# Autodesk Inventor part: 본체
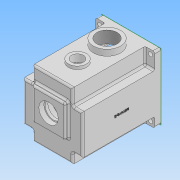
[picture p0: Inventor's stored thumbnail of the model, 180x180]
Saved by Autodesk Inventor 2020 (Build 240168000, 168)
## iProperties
Created: 2022-01
Part Number: 본체
Material: 일반
Document SubType Name: Modeling
Designer: user
Density: 1 g/cm^3
Appearance: 기본값
Author: user
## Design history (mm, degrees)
sketch "스케치1"
  geometry: L1 (-49, -55)-(49, -55); L2 (49, -55)-(49, 55); L3 (49, 55)-(-49, 55); L4 (-49, 55)-(-49, -55); L5 (-49, -55)-(49, 55); L6 (49, -55)-(-49, 55); 1 further point
  constraints: 12 end point, 2 midpoint, 2 parallel, 1 horizontal, 1 perpendicular
  dimensions: "d0" = 98 distance of L3.end L2.end; "d1" = 110 distance of L2.end L1.end
extrude "돌출1" new body sketch "스케치1" distance "d2" = 130; taper "d3" = 0 deg
sketch "스케치2"
  geometry: L1 (-49, -55)-(49, -55) reference; L2 (-27, -21)-(27, -21); L3 (27, -21)-(27, 33); L4 (27, 33)-(-27, 33); L5 (-27, 33)-(-27, -21); L6 (-27, -21)-(27, 33); L7 (27, -21)-(-27, 33); 3 further points
  constraints: 12 end point, 3 midpoint, 2 parallel, 1 horizontal, 1 perpendicular, 1 vertical alignment
  dimensions: "d4" = 54 distance of L3.end L4.end; "d5" = 54 distance of L2.end L3.end; "d7" = 61 distance from line of point (0, 6) L1
extrude "돌출2" join sketch "스케치2" distance "d8" = 7; taper "d9" = 0 deg
sketch "스케치3"
  geometry: L1 (27, 33)-(27, -21) reference; L2 (27, -21)-(-27, -21) reference; L3 (-27, -21)-(-27, 33) reference; L4 (-27, 33)-(27, 33) reference; L5 (-49, -55)-(49, -55) reference; L6 (49, -55)-(49, 55) reference; L7 (49, 55)-(-49, 55) reference; L8 (-49, 55)-(-49, -55) reference; L9 (-49, 55)-(-33, 55); L10 (-33, 55)-(-33, 28); L11 (-33, 28)-(-49, 28); L12 (-49, 28)-(-49, 55); L13 (49, 55)-(33, 55); L14 (33, 55)-(33, 28); L15 (33, 28)-(49, 28); L16 (49, 28)-(49, 55); L17 (-49, -55)-(-33, -55); L18 (-33, -55)-(-33, -38); L19 (-33, -38)-(-49, -38); L20 (-49, -38)-(-49, -55); L21 (49, -55)-(33, -55); L22 (33, -55)-(33, -38); L23 (33, -38)-(49, -38); L24 (49, -38)-(49, -55); 9 further points
  constraints: 32 end point, 8 parallel, 4 horizontal, 4 perpendicular, 1 horizontal alignment, 1 point on line
  dimensions: "d10" = 16 distance of L7.end L9.end; "d11" = 16 distance of L6.end L13.end; "d12" = 16 distance between parallel lines of L8 L18; "d13" = 16 distance between parallel lines of L6 L22; "d14" = 27 distance between parallel lines of L11 L7; "d15" = 17 distance between parallel lines of L19 L5
extrude "돌출3" cut sketch "스케치3" distance "d16" = 120; taper "d17" = 0 deg
sketch "스케치4"
  geometry: L1 (-49, -55)-(49, -55) reference; L2 (-23, 45)-(23, 45); L3 (23, 45)-(23, 30.143); L4 (-23, 30.143)-(-23, 45); A1 r 42 centre (0, -5) between (-23, 30.143) and (23, 30.143); 4 further points
  constraints: 6 end point, 2 point on circle, 2 vertical alignment, 1 centre point, 1 horizontal, 1 midpoint, 1 parallel, 1 perpendicular
  dimensions: "d18" = 50 distance from line of A1.centre L1; "d19" = 84 diameter of A1; "d20" = 50 distance from line of A1.centre L2; "d21" = 46 distance of L2.start L2.end
extrude "돌출4" cut sketch "스케치4" distance "d22" = 121; taper "d23" = 0 deg
sketch "스케치5"
  geometry: L1 (23, 45)-(23, 30.143) reference; L2 (-23, 30.143)-(-23, 45) reference; L3 (-23, 45)-(23, 45) reference; L4 (26, 31.729)-(26, 48); L5 (26, 48)-(-26, 48); L6 (-26, 48)-(-26, 31.729); A1 r 42 centre (0, -5) between (-23, 30.143) and (23, 30.143) reference; A2 r 45 centre (0, -5) between (-26, 31.729) and (26, 31.729); 1 further point
  constraints: 6 end point, 2 point on circle, 1 centre point, 3 other
  dimensions: "d24" = 3 radial gap between concentric circles of A1 A2
extrude "돌출5" cut sketch "스케치5" distance "d25" = 9; taper "d26" = 0 deg
sketch "스케치6"
  geometry: C1 r 21 at (0, 6); C2 r 15 at (0, -25); A1 r 42 centre (0, -5) between (-23, 30.143) and (23, 30.143) reference; 3 further points
  constraints: 2 centre point, 2 vertical alignment
  dimensions: "d27" = 20 distance of C2.centre A1.centre; "d28" = 11 distance of A1.centre C1.centre; "d29" = 42 diameter of C1; "d30" = 30 diameter of C2
extrude "돌출6" join sketch "스케치6" distance "d31" = 7; taper "d32" = 0 deg
sketch "스케치7"
  geometry: A1 r 15 centre (0, -25) between (-8.978, -12.984) and (8.978, -12.984) reference; 1 further point
hole "구멍1" sketch "스케치7" at (0, -25) diameter "d33" = 19; stored, may be unused: countersink angle "d37" = 90 deg, drill point angle "d39" = 0 deg; dims "d34" = 70, "d35" = 22, "d36" = 7, "d38" = 10
sketch "스케치8"
  geometry: A1 r 21 centre (0, 6) between (8.978, -12.984) and (-8.978, -12.984) reference; 2 further points
  constraints: 1 coincident
hole "구멍2" sketch "스케치8" at (0, 6) diameter "d40" = 28; stored, may be unused: countersink angle "d44" = 90 deg, drill point angle "d46" = 0 deg; dims "d41" = 70, "d42" = 35, "d43" = 10, "d45" = 10
sketch "스케치9"
  geometry: C1 r 14 at (0, 6) reference; C2 r 16 at (0, 6); 1 further point
  constraints: 1 centre point, 1 coincident
  dimensions: "d47" = 32 diameter of C2
extrude "돌출7" cut sketch "스케치9" distance "d48" = 8.3; taper "d49" = 0 deg
sketch "스케치10"
  geometry: L1 (-36, -1)-(-41.809, -1); L2 (-36, -9)-(-41.809, -9); A1 r 45 centre (0, -5) between (-26, 31.729) and (26, 31.729) reference; A2 r 42 centre (0, -5) between (-23, 30.143) and (23, 30.143) reference; A3 r 4 centre (-36, -5) between (-36, -1) and (-36, -9); A4 r 42 centre (0, -5) between (-23, 30.143) and (23, 30.143) reference; 3 further points
  constraints: 4 end point, 4 point on circle, 2 horizontal, 2 tangent, 1 centre point, 1 horizontal alignment
  dimensions: "d50" = 8 diameter of A3; "d51" = 36 distance of A3.centre A1.centre
extrude "돌출8" join sketch "스케치10" stored distance "d52" = 8.3; taper "d53" = 0 deg
sketch "스케치11"
  geometry: L1 (98, 0)-(0, 0) reference; L2 (49, 0)-(49, -40); L3 (49, -40)-(49, -89); C1 r 22.5 at (49, -40); C2 r 15 at (49, -89); 1 further point
  constraints: 4 end point, 2 centre point, 2 coincident, 1 midpoint, 1 point on line, 1 vertical
  dimensions: "d66" = 40 distance of L2.start L2.end; "d67" = 49 distance of L2.end L3.end; "d68" = 45 diameter of C1; "d69" = 30 diameter of C2
sketch "스케치12"
  geometry: L1 (-26, 48)-(26, 48) reference; L2 (-49, 55)-(-49, -55) reference; L3 (-49, 55)-(-49, 48); L4 (-49, 48)-(-42, 48); L5 (-42, 48)-(42, 48); L6 (42, 48)-(42, -48); L7 (42, -48)-(-42, -48); L8 (-42, -48)-(-42, 48); 1 further point
  constraints: 12 end point, 2 perpendicular, 2 point on line, 1 horizontal
  dimensions: "d54" = 7 distance of L2.start L3.end; "d55" = 7 distance of L3.end L4.end; "d56" = 84 distance of L4.end L5.end; "d57" = 96 distance of L5.end L6.end; "d58" = 84 distance of L6.end L7.end
hole "구멍3" sketch "스케치12" at (-42, 48), (-42, -48), (42, -48), (42, 48) diameter "d59" = 7; stored, may be unused: countersink angle "d63" = 90 deg, drill point angle "d65" = 0 deg; dims "d60" = 70, "d61" = 35, "d62" = 10, "d64" = 10
extrude "돌출9" join sketch "스케치11" distance "d70" = 10; taper "d71" = 0 deg
extrude "돌출10" join sketch "스케치11" distance "d72" = 5; taper "d73" = 0 deg
sketch "스케치13"
  geometry: C1 r 22.5 at (0, 0) reference; 2 further points
  constraints: 1 coincident
hole "구멍4" sketch "스케치13" at (0, 0) diameter "d74" = 33.376; stored, may be unused: countersink angle "d78" = 90 deg, drill point angle "d80" = 118 deg; dims "d75" = 30, "d76" = 35, "d77" = 10, "d79" = 77.3
sketch "스케치14"
  geometry: L1 (-26, 31.729)-(-26, 48) reference; L2 (-26, 48)-(26, 48) reference; L3 (26, 48)-(26, 31.729) reference; L4 (-49, -55)-(49, -55) reference; L5 (49, -55)-(49, 55) reference; L6 (49, 55)-(-49, 55) reference; L7 (-49, 55)-(-49, -55) reference; C1 r 3.5 at (42, -48) reference; C2 r 3.5 at (-42, 48) reference; C3 r 3.5 at (-42, -48) reference; C4 r 3.5 at (42, 48) reference; A1 r 45 centre (0, -5) between (-26, 31.729) and (26, 31.729) reference; 1 further point
sketch "스케치15"
  geometry: C1 r 15 at (0, 0) reference; 2 further points
  constraints: 1 coincident
hole "구멍5" sketch "스케치15" at (0, 0) diameter "d81" = 20; stored, may be unused: countersink angle "d85" = 90 deg, drill point angle "d87" = 0 deg; dims "d82" = 30, "d83" = 35, "d84" = 10, "d86" = 12
sketch "스케치16"
  geometry: 2 further points
hole "구멍6" sketch "스케치16" at (-1.683, -1.623) diameter "d88" = 30; stored, may be unused: countersink angle "d92" = 90 deg, drill point angle "d94" = 0 deg; dims "d89" = 30, "d90" = 35, "d91" = 10, "d93" = 5
sketch "스케치17"
  geometry: A1 r 4 centre (-36, -5) between (-36, -9) and (-36, -1) reference; 2 further points
  constraints: 1 coincident
hole "구멍7" sketch "스케치17" at (-36, -5) diameter "d95" = 3.242; stored, may be unused: countersink angle "d99" = 90 deg, drill point angle "d101" = 118 deg; dims "d96" = 7, "d97" = 35, "d98" = 10, "d100" = 9
sketch "스케치18"
  geometry: A1 r 4 centre (36, -5) between (36, -1) and (36, -9) reference; 2 further points
  constraints: 1 coincident
hole "구멍8" sketch "스케치18" at (36, -5) diameter "d102" = 3.242; stored, may be unused: countersink angle "d106" = 90 deg, drill point angle "d108" = 118 deg; dims "d103" = 7, "d104" = 35, "d105" = 10, "d107" = 9
fillet "모깎기1" dims "d109" = 6
fillet "모깎기2" dims "d110" = 3
fillet "모깎기3" dims "d111" = 3
fillet "모깎기4" dims "d112" = 3
fillet "모깎기5" dims "d113" = 0.3
fillet "모깎기6" dims "d114" = 3
fillet "모깎기7" dims "d115" = 3
fillet "모깎기8" dims "d116" = 3
fillet "모깎기9" dims "d117" = 3
sketch "스케치19"
  geometry: L1 (-13, 80)-(-127, 80) reference; L2 (-130, 104)-(-130, 83) reference; 2 further points
  constraints: 1 other
  dimensions: "d118" = 65 distance from line of L2 point (-65, 47); "d119" = 33 distance from line of L1 point (-65, 47)
feature "엠보싱1" sketch "스케치19" dims "d120" = 0.5, "d121" = 0
chamfer "모따기1" distance "d122" = 1; stored, may be unused: second distance "d123" = 2, angle "d124" = 45 deg
node "솔리드1"
mirror "미러1"
feature "A9D066F2-1C7D-4E18-AEED-F7BC21143FA4" dims "d33" = 19, "d34" = 70, "d35" = 22, "d36" = 7, "d37" = 90 deg, "d38" = 10, "d39" = 0
